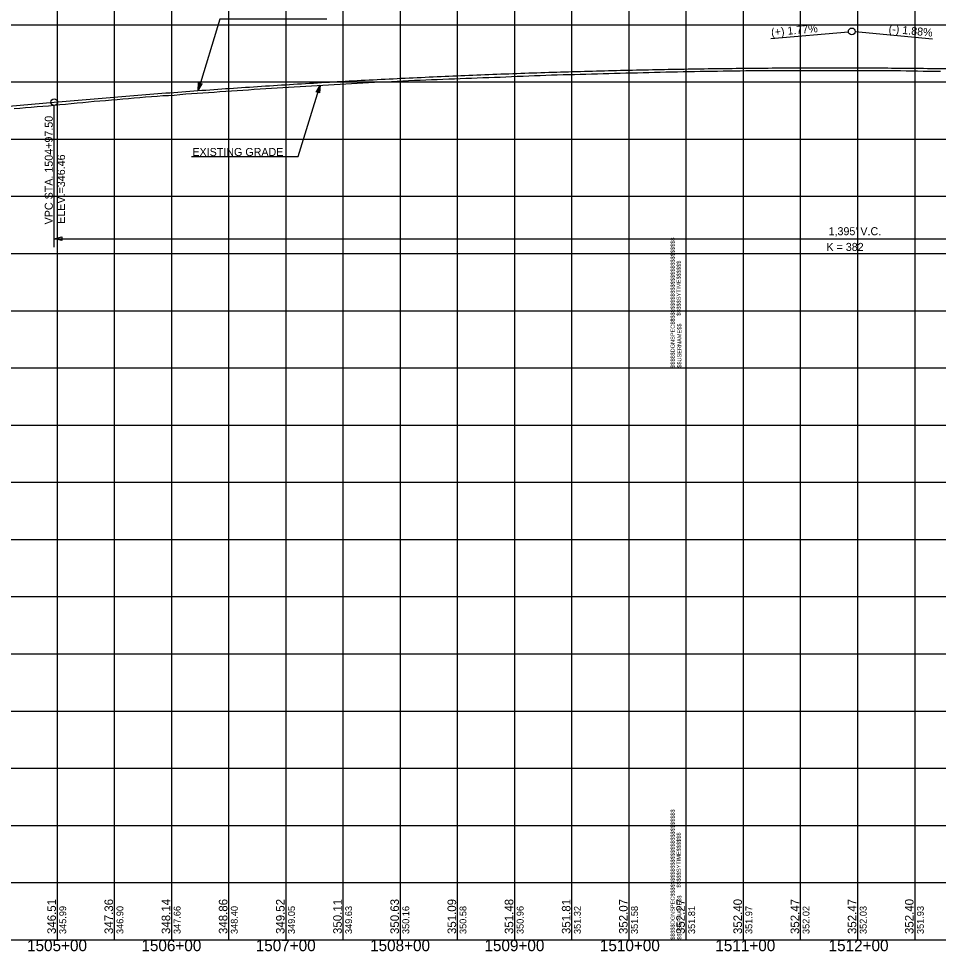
# Model space of a CAD drawing. Extents: x -90830 to 2015517, y -20856 to 836331.
# Drawn here: x 39390 to 40194, y -10807 to -9992 of the extents above; entities that cross this region are included whole.
import ezdxf

# ---------------------------------------------------------------- set-up
doc = ezdxf.new("R2010")
doc.units = 0
for name, color, linetype in [('Level 1', 7, 'Continuous'), ('RD_DDB_GradeTX', 7, 'Continuous'), ('RD_DDB_Profile_Elev', 7, 'Continuous'), ('RD_DDB_Profile_EX', 7, 'Continuous'), ('RD_DDB_Profile_PR', 7, 'Continuous'), ('RD_DDB_StaTX', 7, 'Continuous'), ('RD_DDB_StripGrade', 7, 'Continuous'), ('RD_DDB_VCLbl', 7, 'Continuous'), ('RD_GPK_Profile_Cell', 7, 'Continuous'), ('RD_PD_Final_TX', 7, 'Continuous')]:
    doc.layers.add(name, color=color, linetype=linetype)

msp = doc.modelspace()

# ---------------------------------------------------------------- linework, layer by layer
at = {"layer": 'Level 1'}
for p, q in [((39423.46, -9797.12), (39423.46, -10297.12)), ((39473.46, -9797.12), (39473.46, -10297.12)), ((39523.46, -9797.12), (39523.46, -10297.12)), ((39573.46, -9797.12), (39573.46, -10297.12)), ((39623.46, -9797.12), (39623.46, -10297.12)), ((39673.46, -9797.12), (39673.46, -10297.12)), ((39723.46, -9797.12), (39723.46, -10297.12)), ((39773.46, -9797.12), (39773.46, -10297.12)), ((39823.46, -9797.12), (39823.46, -10297.12)), ((39873.46, -9797.12), (39873.46, -10297.12)), ((39923.46, -9797.12), (39923.46, -10297.12)), ((39973.46, -9797.12), (39973.46, -10297.12)), ((39973.46, -9797.12), (39973.46, -10297.12)), ((39973.46, -9797.12), (39973.46, -10297.12)), ((40023.46, -9797.12), (40023.46, -10297.12)), ((40073.46, -9797.12), (40073.46, -10297.12)), ((40123.46, -9797.12), (40123.46, -10297.12)), ((40173.46, -9797.12), (40173.46, -10297.12)), ((38373.46, -9997.12), (39973.46, -9997.12)), ((39973.46, -9997.12), (41573.46, -9997.12)), ((38373.46, -10047.12), (39973.46, -10047.12)), ((39973.46, -10047.12), (41573.46, -10047.12)), ((38373.46, -10097.12), (39973.46, -10097.12)), ((39973.46, -10097.12), (41573.46, -10097.12)), ((38373.46, -10147.12), (39973.46, -10147.12)), ((39973.46, -10147.12), (41573.46, -10147.12)), ((38373.46, -10197.12), (39973.46, -10197.12)), ((39973.46, -10197.12), (41573.46, -10197.12)), ((38373.46, -10247.12), (39973.46, -10247.12)), ((39973.46, -10247.12), (41573.46, -10247.12)), ((38373.46, -10297.12), (39973.46, -10297.12)), ((38373.46, -10297.12), (39973.46, -10297.12)), ((39423.46, -10297.12), (39423.46, -10797.12)), ((39473.46, -10297.12), (39473.46, -10797.12)), ((39523.46, -10297.12), (39523.46, -10797.12)), ((39573.46, -10297.12), (39573.46, -10797.12)), ((39623.46, -10297.12), (39623.46, -10797.12)), ((39673.46, -10297.12), (39673.46, -10797.12)), ((39723.46, -10297.12), (39723.46, -10797.12)), ((39773.46, -10297.12), (39773.46, -10797.12)), ((39823.46, -10297.12), (39823.46, -10797.12)), ((39873.46, -10297.12), (39873.46, -10797.12)), ((39923.46, -10297.12), (39923.46, -10797.12)), ((39973.46, -10297.12), (39973.46, -10797.12)), ((39973.46, -10297.12), (39973.46, -10797.12)), ((39973.46, -10297.12), (41573.46, -10297.12)), ((39973.46, -10297.12), (41573.46, -10297.12)), ((39973.46, -10297.12), (39973.46, -10797.12)), ((40023.46, -10297.12), (40023.46, -10797.12)), ((40073.46, -10297.12), (40073.46, -10797.12)), ((40123.46, -10297.12), (40123.46, -10797.12)), ((40173.46, -10297.12), (40173.46, -10797.12)), ((38373.46, -10347.12), (39973.46, -10347.12)), ((39973.46, -10347.12), (41573.46, -10347.12)), ((38373.46, -10397.12), (39973.46, -10397.12)), ((39973.46, -10397.12), (41573.46, -10397.12)), ((38373.46, -10447.12), (39973.46, -10447.12)), ((39973.46, -10447.12), (41573.46, -10447.12)), ((38373.46, -10497.12), (39973.46, -10497.12)), ((39973.46, -10497.12), (41573.46, -10497.12)), ((38373.46, -10547.12), (39973.46, -10547.12)), ((39973.46, -10547.12), (41573.46, -10547.12)), ((38373.46, -10597.12), (39973.46, -10597.12)), ((39973.46, -10597.12), (41573.46, -10597.12)), ((38373.46, -10647.12), (39973.46, -10647.12)), ((39973.46, -10647.12), (41573.46, -10647.12)), ((38373.46, -10697.12), (39973.46, -10697.12)), ((39973.46, -10697.12), (41573.46, -10697.12)), ((38373.46, -10747.12), (39973.46, -10747.12)), ((39973.46, -10747.12), (41573.46, -10747.12)), ((38373.46, -10797.12), (39973.46, -10797.12)), ((39973.46, -10797.12), (41573.46, -10797.12))]:
    msp.add_line(p, q, dxfattribs=at)
at = {"layer": 'RD_DDB_GradeTX'}
for p, q in [((40047.74, -10009.23), (40115.47, -10003.23)), ((40189.15, -10009.59), (40121.45, -10003.24))]:
    msp.add_line(p, q, dxfattribs=at)
msp.add_circle((40118.46, -10002.96), 3, dxfattribs=at)
at = {"layer": 'RD_DDB_Profile_EX'}
for points in [[(39920.95, -10039.28), (39925.95, -10039.17), (39930.95, -10039.06), (39935.95, -10038.96), (39940.95, -10038.82), (39945.95, -10038.69), (39950.95, -10038.55), (39955.95, -10038.42), (39960.95, -10038.31), (39965.95, -10038.2), (39970.95, -10038.1), (39975.95, -10038), (39980.95, -10037.9), (39985.95, -10037.81), (39990.95, -10037.71), (39995.95, -10037.61), (40000.95, -10037.55), (40005.95, -10037.49), (40010.95, -10037.43), (40015.95, -10037.37), (40020.95, -10037.3), (40025.95, -10037.24), (40030.95, -10037.18), (40035.95, -10037.11), (40040.95, -10037.1), (40045.95, -10037.08), (40050.95, -10037.07), (40055.95, -10037.06), (40060.95, -10037.05), (40065.95, -10037.04), (40070.95, -10037.04), (40075.95, -10037.03), (40080.95, -10037.03), (40085.95, -10037.02), (40090.95, -10037.02), (40095.95, -10037.02), (40100.95, -10037.01), (40105.95, -10037.01), (40110.95, -10037), (40115.95, -10036.99), (40120.95, -10036.99), (40125.95, -10036.99), (40130.95, -10037), (40135.95, -10037), (40140.95, -10037.04), (40145.95, -10037.08), (40150.95, -10037.12), (40155.95, -10037.16), (40160.95, -10037.25), (40165.95, -10037.34), (40170.95, -10037.43), (40175.95, -10037.52), (40180.95, -10037.56), (40185.95, -10037.6), (40190.95, -10037.63), (40195.95, -10037.66)], [(39420.95, -10067.41), (39425.95, -10066.91), (39430.95, -10066.41), (39435.95, -10065.91), (39440.95, -10065.44), (39445.95, -10064.98), (39450.95, -10064.51), (39455.95, -10064.04), (39460.95, -10063.63), (39465.95, -10063.22), (39470.95, -10062.81), (39475.95, -10062.4), (39480.95, -10061.97), (39485.95, -10061.54), (39490.95, -10061.11), (39495.95, -10060.68), (39500.95, -10060.27), (39505.95, -10059.86), (39510.95, -10059.44), (39515.95, -10059.03), (39520.95, -10059.08), (39525.95, -10058.57), (39530.95, -10058.06), (39535.95, -10057.56), (39540.95, -10057.23), (39545.95, -10056.9), (39550.95, -10056.57), (39555.95, -10056.24), (39560.95, -10055.92), (39565.95, -10055.59), (39570.95, -10055.27), (39575.95, -10054.95), (39580.95, -10054.61), (39585.95, -10054.26), (39590.95, -10053.91), (39595.95, -10053.57), (39600.95, -10053.25), (39605.95, -10052.94), (39610.95, -10052.63), (39615.95, -10052.32), (39620.95, -10052.02), (39625.95, -10051.73), (39630.95, -10051.43), (39635.95, -10051.13), (39640.95, -10050.83), (39645.95, -10050.53), (39650.95, -10050.23), (39655.95, -10049.93), (39660.95, -10049.65), (39665.95, -10049.38), (39670.95, -10049.11), (39675.95, -10048.83), (39680.95, -10048.53), (39685.95, -10048.23), (39690.95, -10047.93), (39695.95, -10047.63), (39700.95, -10047.4), (39705.95, -10047.16), (39710.95, -10046.93), (39715.95, -10046.69), (39720.95, -10046.44), (39725.95, -10046.18), (39730.95, -10045.93), (39735.95, -10045.68), (39740.95, -10045.47), (39745.95, -10045.26), (39750.95, -10045.05), (39755.95, -10044.85), (39760.95, -10044.66), (39765.95, -10044.48), (39770.95, -10044.3), (39775.95, -10044.11), (39780.95, -10043.91), (39785.95, -10043.69), (39790.95, -10043.48), (39795.95, -10043.27), (39800.95, -10043.12), (39805.95, -10042.96), (39810.95, -10042.81), (39815.95, -10042.65), (39820.95, -10042.44), (39825.95, -10042.21), (39830.95, -10041.99), (39835.95, -10041.77), (39840.95, -10041.57), (39845.95, -10041.38), (39850.95, -10041.19), (39855.95, -10040.99), (39860.95, -10040.86), (39865.95, -10040.73), (39870.95, -10040.6), (39875.95, -10040.47), (39880.95, -10040.33), (39885.95, -10040.18), (39890.95, -10040.04), (39895.95, -10039.89), (39900.95, -10039.77), (39905.95, -10039.64), (39910.95, -10039.51), (39915.95, -10039.39), (39920.95, -10039.28)], [(39385.95, -10070.44), (39390.95, -10069.98), (39395.95, -10069.52), (39400.95, -10069.11), (39405.95, -10068.71), (39410.95, -10068.31), (39415.95, -10067.9), (39420.95, -10067.41)]]:
    msp.add_lwpolyline(points, dxfattribs=at)
at = {"layer": 'RD_DDB_Profile_PR'}
msp.add_line((39323.46, -10073.44), (39420.96, -10064.8), dxfattribs=at)
msp.add_spline([(39420.96, -10064.8), (39448.86, -10062.38), (39476.76, -10060.06), (39504.66, -10057.84), (39532.56, -10055.72), (39560.46, -10053.7), (39588.36, -10051.79), (39616.26, -10049.98), (39644.16, -10048.27), (39672.06, -10046.66), (39699.96, -10045.15), (39727.86, -10043.75), (39755.76, -10042.45), (39783.66, -10041.25), (39811.56, -10040.15), (39839.46, -10039.15), (39867.36, -10038.25), (39895.26, -10037.46), (39923.16, -10036.77), (39951.06, -10036.18), (39978.96, -10035.69), (40006.86, -10035.3), (40034.76, -10035.02), (40062.66, -10034.83), (40090.56, -10034.75), (40118.46, -10034.77), (40146.36, -10034.89), (40174.26, -10035.12), (40202.16, -10035.44), (40230.06, -10035.87), (40257.96, -10036.4), (40285.86, -10037.03), (40313.76, -10037.77), (40341.66, -10038.6), (40369.56, -10039.54), (40397.46, -10040.58), (40425.36, -10041.72), (40453.26, -10042.96), (40481.16, -10044.3), (40509.06, -10045.75), (40536.96, -10047.29), (40564.86, -10048.94), (40592.76, -10050.69), (40620.66, -10052.55), (40648.56, -10054.5), (40676.46, -10056.56), (40704.36, -10058.72), (40732.26, -10060.98), (40760.16, -10063.34), (40788.06, -10065.8), (40815.96, -10068.37)], degree=3, dxfattribs=at)
at = {"layer": 'RD_DDB_VCLbl'}
for p, q in [((39420.96, -10191.46), (39420.96, -10067.8)), ((39420.96, -10184.22), (40815.96, -10184.22))]:
    msp.add_line(p, q, dxfattribs=at)
msp.add_circle((39420.96, -10064.8), 3, dxfattribs=at)
at = {"layer": 'RD_GPK_Profile_Cell'}
msp.add_line((4823.46, -10797.12), (75223.46, -10797.12), dxfattribs=at)
at = {"layer": 'RD_PD_Final_TX'}
for p, q in [((39546.85, -10054.52), (39547.19, -10047.85)), ((39548.74, -10048.32), (39546.85, -10054.52)), ((39546.85, -10054.52), (39550.29, -10048.79)), ((39547.19, -10047.85), (39550.29, -10048.79)), ((39653.45, -10050.08), (39650.01, -10055.8)), ((39651.56, -10056.27), (39653.45, -10050.08)), ((39653.45, -10050.08), (39653.11, -10056.75)), ((39653.11, -10056.75), (39650.01, -10055.8))]:
    msp.add_line(p, q, dxfattribs=at)
for points in [[(39659.29, -9992.15), (39565.9, -9992.15), (39546.85, -10054.52)], [(39541.01, -10112.45), (39634.4, -10112.45), (39653.45, -10050.08)], [(39548.67, -10048.38), (39546.91, -10054.15), (39548.65, -10048.33), (39546.94, -10053.87), (39548.57, -10048.34), (39546.94, -10053.67), (39548.49, -10048.33), (39546.95, -10053.43), (39548.43, -10048.3), (39546.97, -10053.08), (39548.35, -10048.26), (39547, -10052.7), (39548.26, -10048.26), (39547.02, -10052.41), (39548.2, -10048.22), (39547.04, -10052.08), (39548.13, -10048.24), (39547.06, -10051.79), (39548.08, -10048.17), (39547.06, -10051.54), (39547.98, -10048.17), (39547.08, -10051.18), (39547.91, -10048.13), (39547.12, -10050.74), (39547.83, -10048.1), (39547.1, -10050.44), (39547.76, -10048.07), (39547.13, -10049.99), (39547.67, -10048.08), (39547.17, -10049.62), (39547.59, -10048.01), (39547.19, -10049.3), (39547.52, -10048.02), (39547.19, -10049.01), (39547.46, -10047.96), (39547.22, -10048.65), (39547.38, -10047.99), (39547.24, -10048.25), (39547.29, -10047.99)], [(39547.01, -10054.13), (39548.76, -10048.41), (39547.12, -10053.94), (39548.84, -10048.43), (39547.21, -10053.75), (39548.9, -10048.42), (39547.33, -10053.59), (39548.95, -10048.45), (39547.46, -10053.4), (39549.01, -10048.46), (39547.58, -10053.21), (39549.06, -10048.47), (39547.71, -10052.98), (39549.13, -10048.48), (39547.87, -10052.71), (39549.22, -10048.52), (39548, -10052.47), (39549.28, -10048.51), (39548.15, -10052.22), (39549.34, -10048.54), (39548.3, -10051.98), (39549.4, -10048.56), (39548.45, -10051.72), (39549.44, -10048.62), (39548.65, -10051.38), (39549.51, -10048.61), (39548.81, -10051.16), (39549.57, -10048.6), (39548.99, -10050.86), (39549.63, -10048.65), (39549.14, -10050.56), (39549.7, -10048.68), (39549.28, -10050.32), (39549.77, -10048.75), (39549.45, -10050.11), (39549.82, -10048.76), (39549.63, -10049.75), (39549.92, -10048.74), (39549.74, -10049.55), (39550.03, -10048.77), (39549.87, -10049.42), (39550.11, -10048.86), (39550.19, -10048.82), (39550.08, -10048.86)], [(39653.28, -10050.47), (39651.54, -10056.18), (39653.18, -10050.66), (39651.46, -10056.16), (39653.08, -10050.84), (39651.4, -10056.17), (39652.96, -10051), (39651.35, -10056.14), (39652.83, -10051.2), (39651.28, -10056.14), (39652.72, -10051.39), (39651.23, -10056.12), (39652.58, -10051.61), (39651.16, -10056.11), (39652.43, -10051.89), (39651.08, -10056.07), (39652.3, -10052.13), (39651.02, -10056.08), (39652.15, -10052.38), (39650.96, -10056.05), (39652, -10052.61), (39650.9, -10056.03), (39651.85, -10052.87), (39650.86, -10055.98), (39651.64, -10053.22), (39650.78, -10055.98), (39651.49, -10053.44), (39650.72, -10055.99), (39651.3, -10053.73), (39650.67, -10055.95), (39651.15, -10054.04), (39650.6, -10055.91), (39651.01, -10054.27), (39650.53, -10055.85), (39650.85, -10054.49), (39650.48, -10055.83), (39650.67, -10054.84), (39650.37, -10055.86), (39650.55, -10055.04), (39650.27, -10055.83), (39650.43, -10055.17), (39650.19, -10055.73), (39650.1, -10055.77), (39650.21, -10055.74)], [(39651.62, -10056.21), (39653.39, -10050.44), (39651.65, -10056.26), (39653.36, -10050.73), (39651.72, -10056.26), (39653.35, -10050.92), (39651.8, -10056.27), (39653.35, -10051.16), (39651.86, -10056.3), (39653.33, -10051.52), (39651.95, -10056.34), (39653.29, -10051.9), (39652.04, -10056.34), (39653.27, -10052.19), (39652.1, -10056.37), (39653.26, -10052.52), (39652.17, -10056.35), (39653.24, -10052.81), (39652.22, -10056.42), (39653.23, -10053.06), (39652.32, -10056.42), (39653.22, -10053.42), (39652.39, -10056.46), (39653.17, -10053.85), (39652.46, -10056.5), (39653.19, -10054.15), (39652.54, -10056.52), (39653.17, -10054.61), (39652.62, -10056.52), (39653.12, -10054.97), (39652.7, -10056.58), (39653.11, -10055.29), (39652.77, -10056.58), (39653.11, -10055.58), (39652.84, -10056.64), (39653.08, -10055.94), (39652.92, -10056.61), (39653.06, -10056.34), (39653, -10056.61)]]:
    msp.add_lwpolyline(points, dxfattribs=at)
msp.add_lwpolyline([(39427.56, -10185.87), (39420.96, -10184.22), (39427.56, -10182.57)], close=True, dxfattribs=at)

# ---------------------------------------------------------------- texts
at = {"layer": 'Level 1'}
for s, p in [('$$$$$DGNSPEC$$$$$$$$$$$$$$$$$$$$$$$$$$$$', (39963.56, -10297.17)), ('$$$$$SYTIME$$$$$$', (39968.86, -10251.57)), ('$$USERNAME$$', (39969.46, -10297.02)), ('$$$$$DGNSPEC$$$$$$$$$$$$$$$$$$$$$$$$$$$$', (39963.56, -10797.17)), ('$$$$$SYTIME$$$$$$', (39968.86, -10751.57)), ('$$USERNAME$$', (39969.46, -10797.02))]:
    msp.add_text(s, height=3.5436, rotation=90, dxfattribs=at).set_placement(p)
at = {"layer": 'RD_DDB_GradeTX'}
for s, rotation, p in [('(+) 1.77%', 5.0663, (40048.23, -10007.18)), ('(-) 1.88%', 354.64309, (40150.47, -10003.96))]:
    msp.add_text(s, height=7, rotation=rotation, dxfattribs=at).set_placement(p)
at = {"layer": 'RD_DDB_Profile_Elev'}
for s, p in [('346.51', (39422.46, -10792.12)), ('347.36', (39472.46, -10792.12)), ('348.14', (39522.46, -10792.12)), ('348.86', (39572.46, -10792.12)), ('349.52', (39622.46, -10792.12)), ('350.11', (39672.46, -10792.12)), ('350.63', (39722.46, -10792.12)), ('351.09', (39772.46, -10792.12)), ('351.48', (39822.46, -10792.12)), ('351.81', (39872.46, -10792.12)), ('352.07', (39922.46, -10792.12)), ('352.27', (39972.46, -10792.12)), ('352.40', (40022.46, -10792.12)), ('352.47', (40072.46, -10792.12)), ('352.47', (40122.46, -10792.12)), ('352.40', (40172.46, -10792.12))]:
    msp.add_text(s, height=7.5, rotation=90, dxfattribs=at).set_placement(p)
at = {"layer": 'RD_DDB_StaTX'}
for s, p in [('1505+00', (39397.21, -10807.12)), ('1506+00', (39497.21, -10807.12)), ('1507+00', (39597.21, -10807.12)), ('1508+00', (39697.21, -10807.12)), ('1509+00', (39797.21, -10807.12)), ('1510+00', (39898.17, -10807.12)), ('1511+00', (39999.13, -10807.12)), ('1512+00', (40098.17, -10807.12))]:
    msp.add_text(s, height=10, dxfattribs=at).set_placement(p)
at = {"layer": 'RD_DDB_StripGrade'}
for s, height, p in [('VPC STA. 1504+97.50 ', 7, (39419.72, -10171.67)), ('ELEV.=346.46', 7, (39430.46, -10171.16)), ('345.99', 6, (39431.46, -10792.12)), ('346.90', 6, (39481.46, -10792.12)), ('347.66', 6, (39531.46, -10792.12)), ('348.40', 6, (39581.46, -10792.12)), ('349.05', 6, (39631.46, -10792.12)), ('349.63', 6, (39681.46, -10792.12)), ('350.16', 6, (39731.46, -10792.12)), ('350.58', 6, (39781.46, -10792.12)), ('350.96', 6, (39831.46, -10792.12)), ('351.32', 6, (39881.46, -10792.12)), ('351.58', 6, (39931.46, -10792.12)), ('351.81', 6, (39981.46, -10792.12)), ('351.97', 6, (40031.46, -10792.12)), ('352.02', 6, (40081.46, -10792.12)), ('352.03', 6, (40131.46, -10792.12)), ('351.93', 6, (40181.46, -10792.12))]:
    msp.add_text(s, height=height, rotation=90, dxfattribs=at).set_placement(p)
at = {"layer": 'RD_DDB_VCLbl'}
for s, p in [("1,395' V.C.", (40098.16, -10181.13)), ('K = 382', (40096.32, -10194.86))]:
    msp.add_text(s, height=7, dxfattribs=at).set_placement(p)
at = {"layer": 'RD_PD_Final_TX'}
msp.add_text('EXISTING GRADE', height=7, dxfattribs=at).set_placement((39541.83, -10111.84))

doc.saveas('drawing.dxf')
